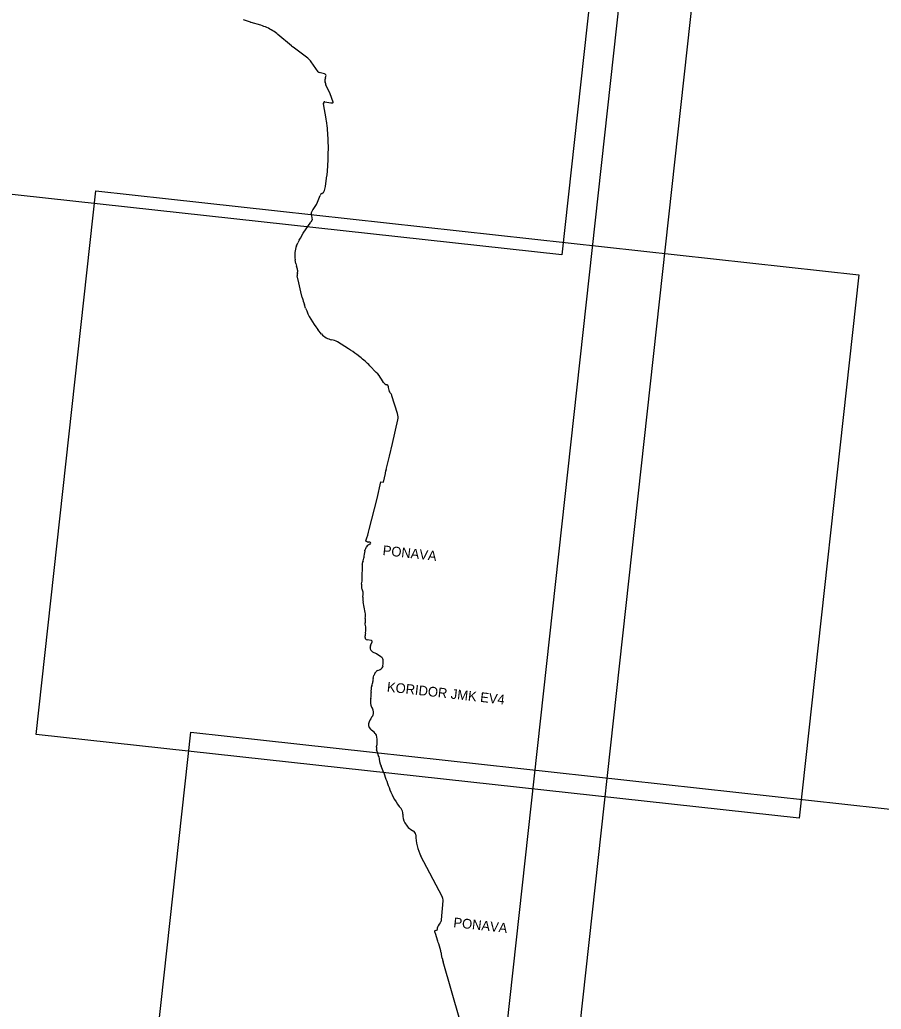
# Model space of a CAD drawing. Extents: x -678204 to -526855, y -1228851 to -1110393.
# Drawn here: x -600965 to -595642, y -1157650 to -1151538 of the extents above; entities that cross this region are included whole.
import ezdxf

# ---------------------------------------------------------------- set-up
doc = ezdxf.new("R2010")
doc.units = 0
for name, color, linetype in [('00_n_cyklo popisy detaily', 7, 'Continuous'), ('00_n_cyklo prujezdne rekreacni hlavni', 7, 'Continuous'), ('00_n_cyklo studie rekreacni hlavni', 7, 'Continuous'), ('00_n_cyklo trasovani rekreacni hlavni', 7, 'Continuous'), ('_HELP', 7, 'Continuous'), ('_HELP BIG', 7, 'Continuous')]:
    doc.layers.add(name, color=color, linetype=linetype)

msp = doc.modelspace()

# ---------------------------------------------------------------- linework, layer by layer
at = {"layer": '00_n_cyklo prujezdne rekreacni hlavni'}
for p, q in [((-599538.6, -1151552.8), (-599582.9, -1151538.8)), ((-599475, -1151572), (-599534.4, -1151554.1)), ((-599401.4, -1151605.6), (-599402, -1151605.3)), ((-599285, -1151698.9), (-599369.4, -1151628.8)), ((-599185.1, -1151775.8), (-599276, -1151706.1)), ((-599121.9, -1151858.5), (-599163.9, -1151798.1)), ((-599081.8, -1151871.2), (-599114.9, -1151863.4)), ((-599076.3, -1151895.5), (-599073.2, -1151887)), ((-599076.5, -1151930.3), (-599078, -1151924)), ((-599047.3, -1151995.6), (-599073.2, -1151939.9)), ((-599028.1, -1152046.4), (-599047.2, -1151995.8)), ((-599087.2, -1152055.7), (-599086.9, -1152049.6)), ((-599071.8, -1152149.6), (-599087.2, -1152057)), ((-599079.9, -1152044), (-599043.6, -1152050)), ((-599033.2, -1152050.6), (-599030.8, -1152050.5)), ((-599069.9, -1152162.7), (-599071, -1152154.7)), ((-599058.1, -1152333.9), (-599059.5, -1152281.8)), ((-599060.1, -1152402.5), (-599059, -1152363.7)), ((-599059, -1152363.7), (-599058.1, -1152333.9)), ((-599066.4, -1152498.9), (-599062.2, -1152439.2)), ((-599062.2, -1152438.9), (-599060.1, -1152403.3)), ((-599076.2, -1152566.2), (-599066.6, -1152500.8)), ((-599129.9, -1152675.4), (-599107.7, -1152622.5)), ((-599098.1, -1152611.1), (-599092.4, -1152607.4)), ((-599081.4, -1152591.5), (-599076.5, -1152567.7)), ((-599152.2, -1152709.5), (-599132.2, -1152679.7)), ((-599164.2, -1152731.8), (-599153.6, -1152711.7))]:
    msp.add_line(p, q, dxfattribs=at)
msp.add_lwpolyline([(-599164.2, -1152731.8), (-599161.8, -1152748.5), (-599158.9, -1152773.8), (-599166.8, -1152788.1)], dxfattribs=at)
for centre, radius, start, end in [((-599447.8, -1151266.9), 300, 252.38742, 253.22349), ((-599561.6, -1151859.3), 300, 57.8477, 73.22349), ((-599561.1, -1151859.6), 300, 50.30432, 57.8477), ((-599093.4, -1151468.1), 300, 230.30432, 232.49299), ((-599246, -1151855.1), 100, 34.75214, 52.49299), ((-599112.1, -1151851.7), 12, 214.75214, 256.70143), ((-599084.5, -1151882.9), 12, 340.13741, 76.70143), ((-599029.3, -1151912.5), 50, 160.13741, 193.26333), ((-599027.8, -1151918.9), 50, 193.26333, 204.8637), ((-599050, -1151996.9), 3, 20.72556, 24.8637), ((-599081.2, -1152056), 6, 176.86364, 189.39084), ((-599080.9, -1152049.9), 6, 80.64451, 176.86364), ((-599035.5, -1152000.6), 50, 260.64451, 272.68378), ((-599030.9, -1152047.5), 3, 272.68378, 20.72556), ((-599367.8, -1152198.6), 300, 8.41108, 9.39084), ((-600059.1, -1152308.9), 1000, 1.55732, 8.41108), ((-599087.2, -1152437.4), 25, 356.00762, 356.60836), ((-599085, -1152401.8), 25, 356.60836, 358.40895), ((-599091.3, -1152497.1), 25, 351.6356, 356.00762), ((-599084.6, -1152632.1), 25, 122.63356, 157.27879), ((-599105.9, -1152586.4), 25, 302.63356, 348.21501), ((-599100.9, -1152562.5), 25, 348.21501, 351.6356), ((-599152.9, -1152665.7), 25, 326.03316, 337.27879), ((-599131.5, -1152723.4), 25, 146.03316, 152.0978)]:
    msp.add_arc(centre, radius, start, end, dxfattribs=at)
at = {"layer": '00_n_cyklo studie rekreacni hlavni'}
for p, q in [((-599212.9, -1152856.2), (-599166.8, -1152788.1)), ((-599198.6, -1153318.3), (-599205.9, -1153297.8)), ((-598695.3, -1153792.7), (-598697.8, -1153792.1)), ((-598677.5, -1153840.1), (-598680.8, -1153834.5)), ((-598680.3, -1154233.5), (-598661.9, -1154154.6)), ((-598818.7, -1154762.5), (-598823.4, -1154760.6)), ((-598802.5, -1154764.3), (-598810.2, -1154764.1)), ((-598830, -1155237), (-598829.6, -1155234.4)), ((-598757.4, -1155981.7), (-598761.4, -1155957.7)), ((-598760.8, -1156031.4), (-598759.6, -1156027)), ((-598756.1, -1156003.2), (-598756.1, -1156000.2)), ((-598355, -1156953.7), (-598486.2, -1156704.7)), ((-598358.3, -1157097.6), (-598349.4, -1156980.8)), ((-598381, -1157230.1), (-598395.8, -1157181.6)), ((-598395.5, -1157162.9), (-598384.6, -1157160)), ((-598363.7, -1157289.8), (-598376.1, -1157246.5)), ((-598354.7, -1157334.1), (-598358.7, -1157311.1)), ((-598245.5, -1157716.1), (-598349.5, -1157356.6))]:
    msp.add_line(p, q, dxfattribs=at)
for points in [[(-599239, -1152900), (-599231.2, -1152886.2), (-599212.9, -1152856.2)], [(-599254.2, -1152933.2), (-599246.7, -1152915.5)], [(-599259.1, -1153043.2), (-599263.5, -1153019.7)], [(-599249.3, -1153078.6), (-599255.2, -1153059)], [(-599249.5, -1153104.2), (-599248.6, -1153101.4), (-599248, -1153099)], [(-599247.5, -1153086.8), (-599247.7, -1153085.2)], [(-599219.4, -1153254.1), (-599228.7, -1153218.5), (-599241.3, -1153162.5), (-599250.2, -1153119)], [(-599099.5, -1153478.9), (-599123.2, -1153450.6)], [(-598933.4, -1153570.1), (-599002.3, -1153527.4)], [(-598862.9, -1153620.9), (-598882.2, -1153606.5)], [(-598762.1, -1153716.2), (-598801.7, -1153675)], [(-598717.4, -1153778), (-598730.4, -1153757)], [(-598673.5, -1153845.3), (-598677.5, -1153840.1)], [(-598630.2, -1153970), (-598664.8, -1153861.4)], [(-598661.9, -1154154.6), (-598628.6, -1154009.6)], [(-598700.7, -1154315.3), (-598680.3, -1154233.5)], [(-598718.1, -1154395), (-598705, -1154339.6), (-598702.3, -1154323.1)], [(-598805.6, -1154686.4), (-598757.2, -1154495.6), (-598733.5, -1154391.8), (-598718.1, -1154395)], [(-598850, -1155006.2), (-598848.6, -1154984.8), (-598847.9, -1154911.6)], [(-598852.8, -1155024.1), (-598852.5, -1155023.1)], [(-598847.7, -1155060.6), (-598849.5, -1155056.9)], [(-598844.9, -1155104.8), (-598843.2, -1155086.2)], [(-598830.3, -1155199.5), (-598843.4, -1155133.1)], [(-598828.4, -1155279.1), (-598829.7, -1155271.2), (-598830.6, -1155263.4)], [(-598827, -1155306.8), (-598826.9, -1155297.8)], [(-598830.9, -1155353.6), (-598830.8, -1155343.7)], [(-598829.3, -1155327.4), (-598828.4, -1155322.6)], [(-598792.2, -1155372.9), (-598818.3, -1155368.5)], [(-598799.3, -1155414.3), (-598799.1, -1155411.4)], [(-598796.8, -1155402.4), (-598787.7, -1155381.2)], [(-598733.1, -1155472.5), (-598760.8, -1155454.8), (-598782.8, -1155443.9)], [(-598719.2, -1155494.8), (-598719.8, -1155492)], [(-598752, -1155557.2), (-598742.2, -1155553.4), (-598736.9, -1155550.7)], [(-598720.4, -1155527.9), (-598718.9, -1155517.1)], [(-598718.6, -1155512.9), (-598718.7, -1155500.5)], [(-598781.7, -1155607.9), (-598779.1, -1155596.8), (-598777.3, -1155589.4)], [(-598768.2, -1155570.7), (-598765.6, -1155567.3), (-598762.8, -1155564.3)]]:
    msp.add_lwpolyline(points, dxfattribs=at)
for centre, radius, start, end in [((-599108.6, -1152974.2), 150, 150.35836, 156.95916), ((-599116.1, -1152991.9), 150, 156.95916, 190.68971), ((-599111.7, -1153015.4), 150, 190.68971, 196.91957), ((-599220.8, -1153113), 30, 162.82445, 191.56647), ((-599297.1, -1153093.2), 50, 9.21168, 16.91957), ((-599277.1, -1153091.6), 30, 345.83588, 9.21168), ((-598735.5, -1153128.3), 500, 194.58209, 199.81561), ((-598791.6, -1153173.7), 432, 199.55647, 219.86417), ((-599021.6, -1153413.8), 101.5, 219.86417, 260.6283), ((-599054.2, -1153611.1), 98.5, 58.21584, 80.6283), ((-599196, -1153993.8), 498.5, 51.00026, 58.21584), ((-599161.3, -1154020.2), 498.5, 43.81925, 53.22815), ((-598902.2, -1153857.8), 199.2, 30.42556, 45.29795), ((-598690.7, -1153761.5), 31.5, 211.72451, 256.8881), ((-598697.2, -1153801), 8.5, 358.87355, 76.8881), ((-598620.7, -1153802.5), 68, 178.87355, 208.00574), ((-598712.5, -1153876.6), 50, 17.66875, 38.72198), ((-598701.7, -1153992.8), 75, 347.0733, 17.66875), ((-598603.6, -1154339.4), 100, 166.04097, 170.56859), ((-599668, -1154472.1), 888.7, 341.39417, 346.04657), ((-598822, -1154756.9), 4, 161.39417, 248.80951), ((-598809.6, -1154739.2), 25, 248.80951, 268.78394), ((-598664.9, -1154867), 174.8, 163.82761, 178.34575), ((-598928.8, -1154790.4), 100, 343.82761, 345.82753), ((-598762, -1154832.6), 72, 149.3899, 165.82753), ((-598802.4, -1154808.6), 25, 140.24326, 149.3899), ((-598783, -1154824.8), 50.3, 111.11574, 140.24326), ((-598802.7, -1154771.2), 6.85, 289.39607, 88.78394), ((-598792.1, -1154801.2), 25, 109.39607, 111.11574), ((-598798.3, -1154900.1), 50, 155.82712, 184.09778), ((-598891.3, -1154858.3), 51.9, 335.82712, 353.86993), ((-598864.5, -1154861.2), 25, 353.86993, 358.34575), ((-598947.9, -1154910.8), 100, 359.50684, 4.09778), ((-598949.8, -1154999.8), 100, 346.50936, 356.31685), ((-598804.1, -1155035.8), 50, 166.50936, 204.99453), ((-598893, -1155081.8), 50, 354.87088, 24.99453), ((-598745.3, -1155113.7), 100, 174.87088, 191.19339), ((-598731.2, -1155252.5), 100, 171.10063, 186.24137), ((-598928.4, -1155219), 100, 351.10063, 11.19339), ((-598926.8, -1155296.4), 100, 359.20905, 9.97443), ((-598927, -1155305.4), 100, 350.12088, 359.20905), ((-598815.9, -1155353.8), 15, 179.49934, 260.48433), ((-598730.8, -1155344.5), 100, 170.12088, 179.49934), ((-598793.2, -1155378.8), 6, 336.81652, 80.48433), ((-598769.4, -1155417), 30, 174.71298, 243.62594), ((-598769.2, -1155414.2), 30, 156.81652, 174.71298), ((-598749.2, -1155497.8), 30, 11.17987, 57.41145), ((-598748.7, -1155500.7), 30, 0.27507, 11.17987), ((-598741.1, -1155585.1), 30, 111.28217, 136.11329), ((-598750.1, -1155523.8), 30, 296.14464, 352.17355), ((-598748.6, -1155513.1), 30, 352.17355, 0.27507), ((-598708.8, -1155625.3), 75, 166.58029, 179.51701), ((-598728.7, -1155601.3), 50, 142.23689, 166.23916), ((-598719.9, -1155680.7), 75, 157.79954, 190.47127), ((-598858.8, -1155624), 75, 337.79954, 359.51701), ((-598718.9, -1155750.2), 79.4, 164.6786, 179.93174), ((-598866.8, -1155707.8), 74.4, 343.29209, 10.47127), ((-598732, -1155754.4), 66.5, 176.31956, 215.34509), ((-598819.7, -1155817.5), 41.5, 338.45352, 36.37631), ((-598665.4, -1155935.9), 153.9, 140.53115, 156.28053), ((-598799.6, -1155825.4), 20, 320.53115, 338.45352), ((-598768.3, -1155891.1), 41.6, 155.84973, 223.72068), ((-642396.4, -1206930), 67103, 49.445657, 49.479712), ((-598781.1, -1155961), 20, 9.3759, 49.44566), ((-598856.1, -1155998), 100, 358.73777, 9.3759), ((-598736.1, -1156038.1), 25.5, 164.90029, 203.02526), ((-598856.1, -1156001), 100, 344.90029, 358.73777), ((-598942.2, -1156126.6), 198.7, 10.64577, 23.26853), ((-598502.9, -1156058.5), 246, 187.31649, 201.36648), ((-610317.5, -1160686.6), 12442.7, 21.18698, 21.39185), ((-593759.4, -1154465.4), 5247.8, 199.18113, 200.3948), ((-598299.3, -1156146.8), 406.5, 201.26629, 220.39126), ((-598647, -1156442.6), 50, 357.39166, 40.39126), ((-598492.8, -1156449.6), 104.4, 177.39166, 207.51432), ((-598487, -1156447.9), 110.3, 206.93073, 244.2006), ((-598548.1, -1156574.2), 30, 1.07658, 64.2006), ((-598209.4, -1156567.8), 308.8, 181.07658, 206.3051), ((-598399.2, -1156977), 50, 355.64035, 27.77599), ((-598365.3, -1157152.4), 20, 154.88002, 182.54313), ((-598183.2, -1157237.8), 221.1, 143.99629, 154.88002), ((-598378.2, -1157096.1), 20, 323.99629, 355.64035), ((-598393.5, -1157170.6), 8, 104.53071, 226.56099), ((-598407.2, -1157185.1), 12, 16.99612, 46.56099), ((-598315.8, -1157150.2), 69.5, 182.54313, 188.12398), ((-599335.1, -1157521.7), 997.7, 16.01172, 16.99612), ((-598563.3, -1157347.1), 207.7, 9.98773, 16.01172), ((-598142.7, -1157296.8), 215.3, 189.98773, 196.13033)]:
    msp.add_arc(centre, radius, start, end, dxfattribs=at)
at = {"layer": '00_n_cyklo trasovani rekreacni hlavni'}
for p, q in [((-599538.6, -1151552.8), (-599582.9, -1151538.8)), ((-599475, -1151572), (-599534.4, -1151554.1)), ((-599401.4, -1151605.6), (-599402, -1151605.3)), ((-599285, -1151698.9), (-599369.4, -1151628.8)), ((-599185.1, -1151775.8), (-599276, -1151706.1)), ((-599121.9, -1151858.5), (-599163.9, -1151798.1)), ((-599081.8, -1151871.2), (-599114.9, -1151863.4)), ((-599076.3, -1151895.5), (-599073.2, -1151887)), ((-599076.5, -1151930.3), (-599078, -1151924)), ((-599047.3, -1151995.6), (-599073.2, -1151939.9)), ((-599028.1, -1152046.4), (-599047.2, -1151995.8)), ((-599087.2, -1152055.7), (-599086.9, -1152049.6)), ((-599071.8, -1152149.6), (-599087.2, -1152057)), ((-599079.9, -1152044), (-599043.6, -1152050)), ((-599033.2, -1152050.6), (-599030.8, -1152050.5)), ((-599069.9, -1152162.7), (-599071, -1152154.7)), ((-599058.1, -1152333.9), (-599059.5, -1152281.8)), ((-599060.1, -1152402.5), (-599059, -1152363.7)), ((-599059, -1152363.7), (-599058.1, -1152333.9)), ((-599066.4, -1152498.9), (-599062.2, -1152439.2)), ((-599062.2, -1152438.9), (-599060.1, -1152403.3)), ((-599076.2, -1152566.2), (-599066.6, -1152500.8)), ((-599129.9, -1152675.4), (-599107.7, -1152622.5)), ((-599098.1, -1152611.1), (-599092.4, -1152607.4)), ((-599081.4, -1152591.5), (-599076.5, -1152567.7)), ((-599152.2, -1152709.5), (-599132.2, -1152679.7)), ((-599164.2, -1152731.8), (-599153.6, -1152711.7)), ((-599212.9, -1152856.2), (-599166.8, -1152788.1)), ((-599198.6, -1153318.3), (-599205.9, -1153297.8)), ((-598695.3, -1153792.7), (-598697.8, -1153792.1)), ((-598677.5, -1153840.1), (-598680.8, -1153834.5)), ((-598680.3, -1154233.5), (-598661.9, -1154154.6)), ((-598818.7, -1154762.5), (-598823.4, -1154760.6)), ((-598802.5, -1154764.3), (-598810.2, -1154764.1)), ((-598830, -1155237), (-598829.6, -1155234.4)), ((-598757.4, -1155981.7), (-598761.4, -1155957.7)), ((-598760.8, -1156031.4), (-598759.6, -1156027)), ((-598756.1, -1156003.2), (-598756.1, -1156000.2)), ((-598355, -1156953.7), (-598486.2, -1156704.7)), ((-598358.3, -1157097.6), (-598349.4, -1156980.8)), ((-598381, -1157230.1), (-598395.8, -1157181.6)), ((-598395.5, -1157162.9), (-598384.6, -1157160)), ((-598363.7, -1157289.8), (-598376.1, -1157246.5)), ((-598354.7, -1157334.1), (-598358.7, -1157311.1)), ((-598245.5, -1157716.1), (-598349.5, -1157356.6))]:
    msp.add_line(p, q, dxfattribs=at)
for points in [[(-599164.2, -1152731.8), (-599161.8, -1152748.5), (-599158.9, -1152773.8), (-599166.8, -1152788.1)], [(-599239, -1152900), (-599231.2, -1152886.2), (-599212.9, -1152856.2)], [(-599254.2, -1152933.2), (-599246.7, -1152915.5)], [(-599259.1, -1153043.2), (-599263.5, -1153019.7)], [(-599249.3, -1153078.6), (-599255.2, -1153059)], [(-599249.5, -1153104.2), (-599248.6, -1153101.4), (-599248, -1153099)], [(-599247.5, -1153086.8), (-599247.7, -1153085.2)], [(-599219.4, -1153254.1), (-599228.7, -1153218.5), (-599241.3, -1153162.5), (-599250.2, -1153119)], [(-599099.5, -1153478.9), (-599123.2, -1153450.6)], [(-598933.4, -1153570.1), (-599002.3, -1153527.4)], [(-598862.9, -1153620.9), (-598882.2, -1153606.5)], [(-598762.1, -1153716.2), (-598801.7, -1153675)], [(-598717.4, -1153778), (-598730.4, -1153757)], [(-598673.5, -1153845.3), (-598677.5, -1153840.1)], [(-598630.2, -1153970), (-598664.8, -1153861.4)], [(-598661.9, -1154154.6), (-598628.6, -1154009.6)], [(-598700.7, -1154315.3), (-598680.3, -1154233.5)], [(-598718.1, -1154395), (-598705, -1154339.6), (-598702.3, -1154323.1)], [(-598805.6, -1154686.4), (-598757.2, -1154495.6), (-598733.5, -1154391.8), (-598718.1, -1154395)], [(-598850, -1155006.2), (-598848.6, -1154984.8), (-598847.9, -1154911.6)], [(-598852.8, -1155024.1), (-598852.5, -1155023.1)], [(-598847.7, -1155060.6), (-598849.5, -1155056.9)], [(-598844.9, -1155104.8), (-598843.2, -1155086.2)], [(-598830.3, -1155199.5), (-598843.4, -1155133.1)], [(-598828.4, -1155279.1), (-598829.7, -1155271.2), (-598830.6, -1155263.4)], [(-598827, -1155306.8), (-598826.9, -1155297.8)], [(-598830.9, -1155353.6), (-598830.8, -1155343.7)], [(-598829.3, -1155327.4), (-598828.4, -1155322.6)], [(-598792.2, -1155372.9), (-598818.3, -1155368.5)], [(-598799.3, -1155414.3), (-598799.1, -1155411.4)], [(-598796.8, -1155402.4), (-598787.7, -1155381.2)], [(-598733.1, -1155472.5), (-598760.8, -1155454.8), (-598782.8, -1155443.9)], [(-598719.2, -1155494.8), (-598719.8, -1155492)], [(-598752, -1155557.2), (-598742.2, -1155553.4), (-598736.9, -1155550.7)], [(-598720.4, -1155527.9), (-598718.9, -1155517.1)], [(-598718.6, -1155512.9), (-598718.7, -1155500.5)], [(-598781.7, -1155607.9), (-598779.1, -1155596.8), (-598777.3, -1155589.4)], [(-598768.2, -1155570.7), (-598765.6, -1155567.3), (-598762.8, -1155564.3)]]:
    msp.add_lwpolyline(points, dxfattribs=at)
for centre, radius, start, end in [((-599447.8, -1151266.9), 300, 252.38742, 253.22349), ((-599561.6, -1151859.3), 300, 57.8477, 73.22349), ((-599561.1, -1151859.6), 300, 50.30432, 57.8477), ((-599093.4, -1151468.1), 300, 230.30432, 232.49299), ((-599246, -1151855.1), 100, 34.75214, 52.49299), ((-599112.1, -1151851.7), 12, 214.75214, 256.70143), ((-599084.5, -1151882.9), 12, 340.13741, 76.70143), ((-599029.3, -1151912.5), 50, 160.13741, 193.26333), ((-599027.8, -1151918.9), 50, 193.26333, 204.8637), ((-599050, -1151996.9), 3, 20.72556, 24.8637), ((-599081.2, -1152056), 6, 176.86364, 189.39084), ((-599080.9, -1152049.9), 6, 80.64451, 176.86364), ((-599035.5, -1152000.6), 50, 260.64451, 272.68378), ((-599030.9, -1152047.5), 3, 272.68378, 20.72556), ((-599367.8, -1152198.6), 300, 8.41108, 9.39084), ((-600059.1, -1152308.9), 1000, 1.55732, 8.41108), ((-599087.2, -1152437.4), 25, 356.00762, 356.60836), ((-599085, -1152401.8), 25, 356.60836, 358.40895), ((-599091.3, -1152497.1), 25, 351.6356, 356.00762), ((-599084.6, -1152632.1), 25, 122.63356, 157.27879), ((-599105.9, -1152586.4), 25, 302.63356, 348.21501), ((-599100.9, -1152562.5), 25, 348.21501, 351.6356), ((-599152.9, -1152665.7), 25, 326.03316, 337.27879), ((-599131.5, -1152723.4), 25, 146.03316, 152.0978), ((-599108.6, -1152974.2), 150, 150.35836, 156.95916), ((-599116.1, -1152991.9), 150, 156.95916, 190.68971), ((-599111.7, -1153015.4), 150, 190.68971, 196.91957), ((-599220.8, -1153113), 30, 162.82445, 191.56647), ((-599297.1, -1153093.2), 50, 9.21168, 16.91957), ((-599277.1, -1153091.6), 30, 345.83588, 9.21168), ((-598735.5, -1153128.3), 500, 194.58209, 199.81561), ((-598791.6, -1153173.7), 432, 199.55647, 219.86417), ((-599021.6, -1153413.8), 101.5, 219.86417, 260.6283), ((-599054.2, -1153611.1), 98.5, 58.21584, 80.6283), ((-599196, -1153993.8), 498.5, 51.00026, 58.21584), ((-599161.3, -1154020.2), 498.5, 43.81925, 53.22815), ((-598902.2, -1153857.8), 199.2, 30.42556, 45.29795), ((-598690.7, -1153761.5), 31.5, 211.72451, 256.8881), ((-598697.2, -1153801), 8.5, 358.87355, 76.8881), ((-598620.7, -1153802.5), 68, 178.87355, 208.00574), ((-598712.5, -1153876.6), 50, 17.66875, 38.72198), ((-598701.7, -1153992.8), 75, 347.0733, 17.66875), ((-598603.6, -1154339.4), 100, 166.04097, 170.56859), ((-599668, -1154472.1), 888.7, 341.39417, 346.04657), ((-598822, -1154756.9), 4, 161.39417, 248.80951), ((-598809.6, -1154739.2), 25, 248.80951, 268.78394), ((-598664.9, -1154867), 174.8, 163.82761, 178.34575), ((-598928.8, -1154790.4), 100, 343.82761, 345.82753), ((-598762, -1154832.6), 72, 149.3899, 165.82753), ((-598802.4, -1154808.6), 25, 140.24326, 149.3899), ((-598783, -1154824.8), 50.3, 111.11574, 140.24326), ((-598802.7, -1154771.2), 6.85, 289.39607, 88.78394), ((-598792.1, -1154801.2), 25, 109.39607, 111.11574), ((-598798.3, -1154900.1), 50, 155.82712, 184.09778), ((-598891.3, -1154858.3), 51.9, 335.82712, 353.86993), ((-598864.5, -1154861.2), 25, 353.86993, 358.34575), ((-598947.9, -1154910.8), 100, 359.50684, 4.09778), ((-598949.8, -1154999.8), 100, 346.50936, 356.31685), ((-598804.1, -1155035.8), 50, 166.50936, 204.99453), ((-598893, -1155081.8), 50, 354.87088, 24.99453), ((-598745.3, -1155113.7), 100, 174.87088, 191.19339), ((-598731.2, -1155252.5), 100, 171.10063, 186.24137), ((-598928.4, -1155219), 100, 351.10063, 11.19339), ((-598926.8, -1155296.4), 100, 359.20905, 9.97443), ((-598927, -1155305.4), 100, 350.12088, 359.20905), ((-598815.9, -1155353.8), 15, 179.49934, 260.48433), ((-598730.8, -1155344.5), 100, 170.12088, 179.49934), ((-598793.2, -1155378.8), 6, 336.81652, 80.48433), ((-598769.4, -1155417), 30, 174.71298, 243.62594), ((-598769.2, -1155414.2), 30, 156.81652, 174.71298), ((-598749.2, -1155497.8), 30, 11.17987, 57.41145), ((-598748.7, -1155500.7), 30, 0.27507, 11.17987), ((-598741.1, -1155585.1), 30, 111.28217, 136.11329), ((-598750.1, -1155523.8), 30, 296.14464, 352.17355), ((-598748.6, -1155513.1), 30, 352.17355, 0.27507), ((-598708.8, -1155625.3), 75, 166.58029, 179.51701), ((-598728.7, -1155601.3), 50, 142.23689, 166.23916), ((-598719.9, -1155680.7), 75, 157.79954, 190.47127), ((-598858.8, -1155624), 75, 337.79954, 359.51701), ((-598718.9, -1155750.2), 79.4, 164.6786, 179.93174), ((-598866.8, -1155707.8), 74.4, 343.29209, 10.47127), ((-598732, -1155754.4), 66.5, 176.31956, 215.34509), ((-598819.7, -1155817.5), 41.5, 338.45352, 36.37631), ((-598665.4, -1155935.9), 153.9, 140.53115, 156.28053), ((-598799.6, -1155825.4), 20, 320.53115, 338.45352), ((-598768.3, -1155891.1), 41.6, 155.84973, 223.72068), ((-642396.4, -1206930), 67103, 49.445657, 49.479712), ((-598781.1, -1155961), 20, 9.3759, 49.44566), ((-598856.1, -1155998), 100, 358.73777, 9.3759), ((-598736.1, -1156038.1), 25.5, 164.90029, 203.02526), ((-598856.1, -1156001), 100, 344.90029, 358.73777), ((-598942.2, -1156126.6), 198.7, 10.64577, 23.26853), ((-598502.9, -1156058.5), 246, 187.31649, 201.36648), ((-610317.5, -1160686.6), 12442.7, 21.18698, 21.39185), ((-593759.4, -1154465.4), 5247.8, 199.18113, 200.3948), ((-598299.3, -1156146.8), 406.5, 201.26629, 220.39126), ((-598647, -1156442.6), 50, 357.39166, 40.39126), ((-598492.8, -1156449.6), 104.4, 177.39166, 207.51432), ((-598487, -1156447.9), 110.3, 206.93073, 244.2006), ((-598548.1, -1156574.2), 30, 1.07658, 64.2006), ((-598209.4, -1156567.8), 308.8, 181.07658, 206.3051), ((-598399.2, -1156977), 50, 355.64035, 27.77599), ((-598365.3, -1157152.4), 20, 154.88002, 182.54313), ((-598183.2, -1157237.8), 221.1, 143.99629, 154.88002), ((-598378.2, -1157096.1), 20, 323.99629, 355.64035), ((-598393.5, -1157170.6), 8, 104.53071, 226.56099), ((-598407.2, -1157185.1), 12, 16.99612, 46.56099), ((-598315.8, -1157150.2), 69.5, 182.54313, 188.12398), ((-599335.1, -1157521.7), 997.7, 16.01172, 16.99612), ((-598563.3, -1157347.1), 207.7, 9.98773, 16.01172), ((-598142.7, -1157296.8), 215.3, 189.98773, 196.13033)]:
    msp.add_arc(centre, radius, start, end, dxfattribs=at)
at = {"layer": '_HELP'}
for points in [[(-601960.4, -1149114.5), (-597245.8, -1149632.2), (-597614.5, -1152989.7), (-602329, -1152472)], [(-600495, -1152595.3), (-595780.4, -1153113), (-596149.1, -1156470.5), (-600863.7, -1155952.8)], [(-599907, -1155939.4), (-595192.5, -1156457.1), (-595561.2, -1159814.6), (-600275.7, -1159296.9)]]:
    msp.add_lwpolyline(points, close=True, dxfattribs=at)
at = {"layer": '_HELP BIG'}
for points in [[(-617877.4, -1157614.7), (-614771.3, -1129327.4), (-594626.3, -1131539.4), (-597732.4, -1159826.8)], [(-598180, -1159809.1), (-595073.9, -1131521.8), (-574928.9, -1133733.9), (-578035.1, -1162021.2)]]:
    msp.add_lwpolyline(points, close=True, dxfattribs=at)

# ---------------------------------------------------------------- texts
at = {"layer": '00_n_cyklo popisy detaily'}
for s, p in [('PONAVA', (-598724.8, -1154843.9)), ('KORIDOR JMK EV4', (-598698.3, -1155687.2)), ('PONAVA', (-598287.7, -1157142.4))]:
    msp.add_text(s, height=60, rotation=353.68355, dxfattribs=at).set_placement(p)

doc.saveas('drawing.dxf')
